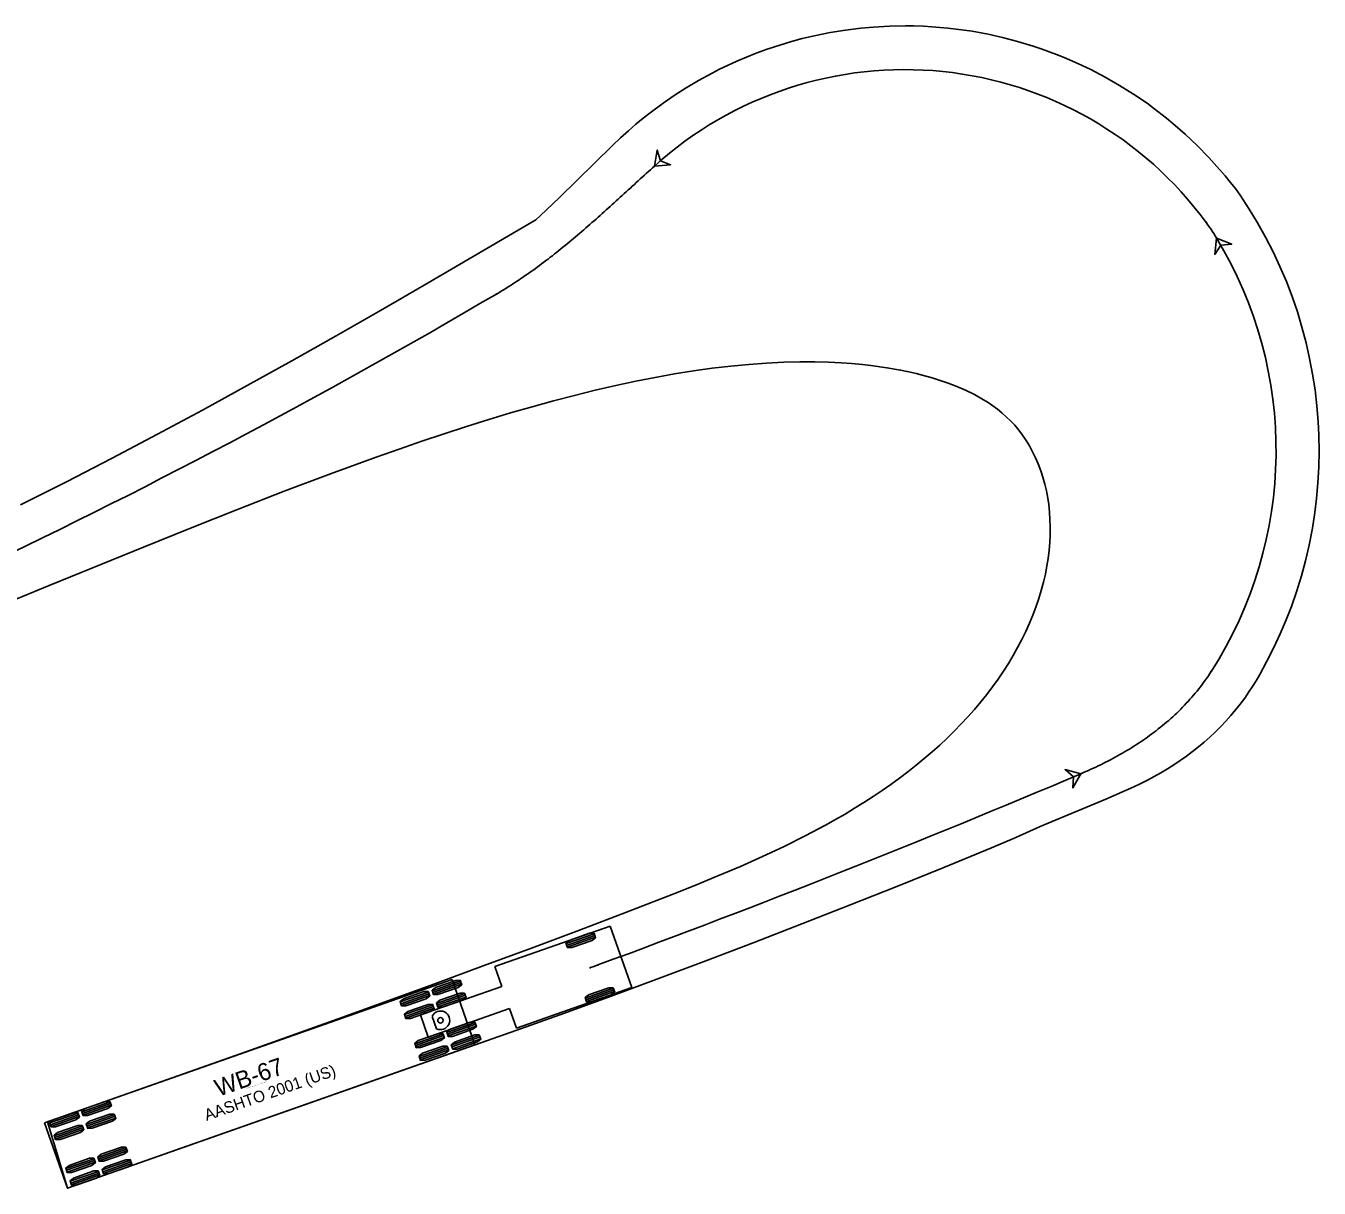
# Model space of a CAD drawing. Extents: x 2175591 to 2194071, y 76570 to 86955.
# Drawn here: x 2193912.2 to 2194070.9, y 86806.6 to 86949.2 of the extents above; entities that cross this region are included whole.
import ezdxf

# ---------------------------------------------------------------- set-up
doc = ezdxf.new("R2010")
doc.units = 0
doc.layers.add('C-UTIL-STRM-TEXT', color=7, linetype='Continuous')

msp = doc.modelspace()

# ---------------------------------------------------------------- linework, layer by layer
at = {"layer": 'C-UTIL-STRM-TEXT'}
for p, q in [((2193983.91, 86838.76), (2193969.76, 86833.78)), ((2193981.95, 86837.82), (2193978.49, 86836.6)), ((2193982.02, 86837.6), (2193978.56, 86836.39)), ((2193982.1, 86837.39), (2193978.64, 86836.17)), ((2193986.57, 86831.21), (2193983.91, 86838.76)), ((2193983.91, 86838.76), (2193983.91, 86838.76)), ((2193969.76, 86833.78), (2193970.61, 86831.36)), ((2193964.49, 86832.19), (2193914.49, 86814.61)), ((2193970.61, 86831.36), (2193960.63, 86827.85)), ((2193965.51, 86832.04), (2193962.06, 86830.83)), ((2193965.59, 86831.83), (2193962.13, 86830.61)), ((2193965.67, 86831.61), (2193962.21, 86830.4)), ((2193967.31, 86824.17), (2193964.49, 86832.19)), ((2193964.49, 86832.19), (2193964.49, 86832.19)), ((2193972.42, 86826.23), (2193986.57, 86831.21)), ((2193984.29, 86831.14), (2193980.84, 86829.92)), ((2193961.58, 86830.66), (2193958.12, 86829.45)), ((2193961.66, 86830.45), (2193958.2, 86829.23)), ((2193961.74, 86830.23), (2193958.28, 86829.01)), ((2193966.06, 86830.49), (2193962.6, 86829.27)), ((2193966.14, 86830.27), (2193962.68, 86829.06)), ((2193966.21, 86830.05), (2193962.75, 86828.84)), ((2193984.37, 86830.92), (2193980.91, 86829.71)), ((2193984.45, 86830.71), (2193980.99, 86829.49)), ((2193962.13, 86829.11), (2193958.67, 86827.89)), ((2193962.21, 86828.89), (2193958.75, 86827.67)), ((2193962.28, 86828.67), (2193958.82, 86827.46)), ((2193960.63, 86827.85), (2193961.58, 86825.14)), ((2193961.58, 86825.14), (2193971.56, 86828.65)), ((2193971.56, 86828.65), (2193972.42, 86826.23)), ((2193962.04, 86827.68), (2193962.58, 86826.16)), ((2193967.32, 86826.92), (2193963.86, 86825.7)), ((2193967.39, 86826.7), (2193963.93, 86825.49)), ((2193967.47, 86826.49), (2193964.01, 86825.27)), ((2193963.39, 86825.54), (2193959.93, 86824.32)), ((2193963.46, 86825.32), (2193960, 86824.1)), ((2193963.54, 86825.1), (2193960.08, 86823.89)), ((2193967.86, 86825.36), (2193964.4, 86824.15)), ((2193967.94, 86825.15), (2193964.48, 86823.93)), ((2193968.02, 86824.93), (2193964.56, 86823.71)), ((2193917.31, 86806.59), (2193967.31, 86824.17)), ((2193963.93, 86823.98), (2193960.47, 86822.76)), ((2193964.01, 86823.76), (2193960.55, 86822.55)), ((2193964.08, 86823.55), (2193960.63, 86822.33)), ((2193922.51, 86817.19), (2193919.05, 86815.97)), ((2193922.58, 86816.97), (2193919.12, 86815.76)), ((2193922.66, 86816.76), (2193919.2, 86815.54)), ((2193918.58, 86815.81), (2193915.12, 86814.59)), ((2193918.65, 86815.59), (2193915.19, 86814.37)), ((2193918.73, 86815.37), (2193915.27, 86814.16)), ((2193923.05, 86815.63), (2193919.6, 86814.42)), ((2193923.13, 86815.42), (2193919.67, 86814.2)), ((2193923.21, 86815.2), (2193919.75, 86813.98)), ((2193914.49, 86814.61), (2193917.31, 86806.59)), ((2193919.12, 86814.25), (2193915.66, 86813.03)), ((2193919.2, 86814.03), (2193915.74, 86812.82)), ((2193919.28, 86813.82), (2193915.82, 86812.6)), ((2193924.47, 86811.59), (2193921.02, 86810.37)), ((2193924.55, 86811.37), (2193921.09, 86810.16)), ((2193924.63, 86811.16), (2193921.17, 86809.94)), ((2193920.54, 86810.21), (2193917.09, 86808.99)), ((2193920.62, 86809.99), (2193917.16, 86808.78)), ((2193920.7, 86809.78), (2193917.24, 86808.56)), ((2193925.02, 86810.03), (2193921.56, 86808.82)), ((2193925.1, 86809.82), (2193921.64, 86808.6)), ((2193925.17, 86809.6), (2193921.72, 86808.39)), ((2193921.09, 86808.65), (2193917.63, 86807.44)), ((2193921.17, 86808.44), (2193917.71, 86807.22)), ((2193921.24, 86808.22), (2193917.78, 86807))]:
    msp.add_line(p, q, dxfattribs=at)
for points in [[(2193911.53, 86890.46), (2193917.16, 86893.3), (2193922.77, 86896.2), (2193928.34, 86899.13), (2193933.87, 86902.1), (2193939.35, 86905.1), (2193944.81, 86908.13), (2193950.27, 86911.22), (2193955.7, 86914.33), (2193961.07, 86917.44), (2193974.76, 86925.45), (2193975.34, 86925.96), (2193977.64, 86928.13), (2193979.87, 86930.3), (2193984.16, 86934.53), (2193985.17, 86935.49), (2193986.14, 86936.37), (2193987.07, 86937.18), (2193987.96, 86937.92), (2193988.82, 86938.59), (2193990.42, 86939.78), (2193991.89, 86940.79), (2193993.24, 86941.65), (2193994.73, 86942.53), (2193996.43, 86943.45), (2193997.34, 86943.92), (2193998.29, 86944.38), (2193999.45, 86944.9), (2194000.64, 86945.41), (2194001.84, 86945.89), (2194003.18, 86946.38), (2194004.71, 86946.88), (2194006.16, 86947.32), (2194007.49, 86947.68), (2194009.16, 86948.07), (2194010.92, 86948.42), (2194012.77, 86948.72), (2194014.69, 86948.96), (2194016.22, 86949.1), (2194018.17, 86949.21), (2194020.14, 86949.25), (2194021.12, 86949.24), (2194022.37, 86949.2), (2194023.37, 86949.14), (2194025.36, 86948.97), (2194026.36, 86948.86), (2194028.34, 86948.58), (2194030.31, 86948.21), (2194032.05, 86947.83), (2194033.91, 86947.34), (2194035.84, 86946.76), (2194036.8, 86946.44), (2194038.7, 86945.74), (2194039.64, 86945.36), (2194041.3, 86944.64), (2194042.9, 86943.88), (2194044.68, 86942.95), (2194046.43, 86941.94), (2194048.13, 86940.87), (2194049.8, 86939.74), (2194050.61, 86939.14), (2194052.21, 86937.91), (2194052.98, 86937.27), (2194054.5, 86935.94), (2194055.97, 86934.55), (2194057.38, 86933.11), (2194058.06, 86932.37), (2194059.38, 86930.85), (2194060.02, 86930.07), (2194060.64, 86929.27), (2194061.23, 86928.45), (2194062.34, 86926.77), (2194063.38, 86925.06), (2194064.36, 86923.31), (2194065.27, 86921.52), (2194066.12, 86919.72), (2194066.9, 86917.88), (2194067.61, 86916.03), (2194068.25, 86914.15), (2194068.82, 86912.26), (2194069.33, 86910.35), (2194069.76, 86908.43), (2194070.13, 86906.51), (2194070.42, 86904.57), (2194070.65, 86902.63), (2194070.81, 86900.68), (2194070.89, 86899.01), (2194070.93, 86897.05), (2194070.89, 86895.1), (2194070.78, 86893.16), (2194070.61, 86891.22), (2194070.4, 86889.51), (2194070.1, 86887.59), (2194069.7, 86885.52), (2194069.25, 86883.6), (2194068.75, 86881.74), (2194068.14, 86879.78), (2194067.52, 86877.99), (2194066.88, 86876.34), (2194066.15, 86874.63), (2194065.37, 86872.93), (2194064.52, 86871.27), (2194063.64, 86869.65), (2194063.18, 86868.86), (2194062.75, 86868.16), (2194062.31, 86867.5), (2194061.79, 86866.75), (2194061.25, 86866.01), (2194060.68, 86865.29), (2194060.09, 86864.59), (2194059.47, 86863.91), (2194058.84, 86863.24), (2194058.19, 86862.59), (2194057.51, 86861.95), (2194056.82, 86861.34), (2194056.11, 86860.74), (2194055.38, 86860.17), (2194054.64, 86859.61), (2194053.88, 86859.07), (2194053.1, 86858.55), (2194052.31, 86858.05), (2194051.51, 86857.57), (2194050.69, 86857.1), (2194049.87, 86856.66), (2194049.03, 86856.24), (2194048.18, 86855.83), (2194044.76, 86854.35), (2194036.7, 86850.96), (2194033.7, 86849.62), (2194030.72, 86848.35), (2194024.84, 86845.94), (2194019.07, 86843.62), (2194013.3, 86841.32), (2194007.42, 86839.02), (2194001.44, 86836.71), (2193995.66, 86834.51), (2193989.63, 86832.25), (2193983.69, 86830.05), (2193977.72, 86827.88), (2193971.76, 86825.75), (2193917.31, 86806.59), (2193914.83, 86814.73), (2193914.83, 86814.73)], [(2193989.33, 86932.03), (2193989.08, 86931.81), (2193988.84, 86931.59), (2193988.59, 86931.36), (2193988.34, 86931.14), (2193988.1, 86930.91), (2193987.85, 86930.69), (2193987.6, 86930.46), (2193987.36, 86930.24), (2193987.11, 86930.01), (2193986.87, 86929.79), (2193986.62, 86929.56), (2193986.38, 86929.34), (2193986.13, 86929.11), (2193985.88, 86928.89), (2193985.64, 86928.66), (2193985.39, 86928.44), (2193985.14, 86928.21), (2193984.9, 86927.99), (2193984.65, 86927.77), (2193984.4, 86927.54), (2193984.16, 86927.32), (2193983.91, 86927.09), (2193983.66, 86926.87), (2193983.42, 86926.65), (2193983.17, 86926.42), (2193982.92, 86926.2), (2193982.67, 86925.98), (2193982.42, 86925.76), (2193982.17, 86925.54), (2193981.92, 86925.32), (2193981.67, 86925.1), (2193981.42, 86924.88), (2193981.17, 86924.66), (2193980.92, 86924.44), (2193980.67, 86924.22), (2193980.41, 86924), (2193980.16, 86923.79), (2193979.91, 86923.57), (2193979.65, 86923.36), (2193979.4, 86923.14), (2193979.14, 86922.93), (2193978.88, 86922.71), (2193978.63, 86922.5), (2193978.37, 86922.29), (2193978.11, 86922.08), (2193977.85, 86921.87), (2193977.59, 86921.66), (2193977.33, 86921.45), (2193977.07, 86921.25), (2193976.81, 86921.04), (2193976.54, 86920.84), (2193976.28, 86920.63), (2193976.02, 86920.43), (2193975.75, 86920.23), (2193975.48, 86920.03), (2193975.22, 86919.83), (2193974.95, 86919.63), (2193974.68, 86919.44), (2193974.41, 86919.24), (2193974.14, 86919.05), (2193973.86, 86918.86), (2193973.59, 86918.67), (2193973.32, 86918.48), (2193973.04, 86918.29), (2193972.76, 86918.1), (2193972.49, 86917.92), (2193972.21, 86917.74), (2193971.93, 86917.55), (2193971.65, 86917.38), (2193971.37, 86917.2), (2193971.08, 86917.02), (2193970.8, 86916.85), (2193970.51, 86916.67), (2193970.23, 86916.5), (2193969.94, 86916.33)], [(2194058.34, 86923.19), (2194058.16, 86923.48), (2194057.99, 86923.76), (2194057.81, 86924.04), (2194057.62, 86924.32), (2194057.43, 86924.59), (2194057.24, 86924.87), (2194057.05, 86925.14)], [(2193914.83, 86814.73), (2193938.63, 86823.12), (2193950.52, 86827.37), (2193962.39, 86831.68), (2193968.32, 86833.86), (2193974.23, 86836.06), (2193980.13, 86838.27), (2193985.92, 86840.47), (2193991.7, 86842.71), (2193994.3, 86843.75), (2193997.12, 86844.91), (2193999.9, 86846.09), (2194002.62, 86847.3), (2194005.27, 86848.54), (2194007.85, 86849.83), (2194010.34, 86851.15), (2194011.56, 86851.83), (2194012.74, 86852.51), (2194013.91, 86853.21), (2194015.05, 86853.92), (2194016.17, 86854.65), (2194017.28, 86855.39), (2194018.36, 86856.14), (2194019.42, 86856.91), (2194020.45, 86857.7), (2194021.47, 86858.5), (2194022.45, 86859.31), (2194023.42, 86860.13), (2194024.35, 86860.97), (2194025.26, 86861.82), (2194026.14, 86862.69), (2194027, 86863.57), (2194027.82, 86864.46), (2194028.62, 86865.36), (2194029.39, 86866.28), (2194030.13, 86867.2), (2194030.84, 86868.14), (2194031.52, 86869.08), (2194032.17, 86870.04), (2194032.78, 86871), (2194033.37, 86871.97), (2194033.92, 86872.95), (2194034.43, 86873.93), (2194034.92, 86874.92), (2194035.37, 86875.92), (2194035.78, 86876.92), (2194036.16, 86877.92), (2194036.51, 86878.95), (2194036.82, 86879.95), (2194037.09, 86880.96), (2194037.32, 86881.96), (2194037.51, 86882.96), (2194037.66, 86883.88), (2194037.78, 86884.88), (2194037.86, 86885.84), (2194037.91, 86886.79), (2194037.92, 86887.74), (2194037.89, 86888.66), (2194037.83, 86889.58), (2194037.73, 86890.49), (2194037.61, 86891.28), (2194037.45, 86892.16), (2194037.25, 86893.01), (2194037.02, 86893.84), (2194036.76, 86894.65), (2194036.45, 86895.48), (2194036.12, 86896.24), (2194035.76, 86896.98), (2194035.38, 86897.69), (2194034.96, 86898.37), (2194034.52, 86899.01), (2194034.06, 86899.63), (2194033.57, 86900.22), (2194033.06, 86900.77), (2194032.53, 86901.28), (2194031.99, 86901.76), (2194031.43, 86902.21), (2194030.87, 86902.62), (2194030.3, 86903.01), (2194029.73, 86903.36), (2194028.61, 86903.99), (2194027.51, 86904.53), (2194026.44, 86904.99), (2194025.41, 86905.39), (2194024.41, 86905.74), (2194023.44, 86906.04), (2194022.36, 86906.35), (2194021.46, 86906.58), (2194020.57, 86906.78), (2194019.55, 86907), (2194017.88, 86907.29), (2194015.91, 86907.57), (2194014.89, 86907.68), (2194013.54, 86907.81), (2194012.25, 86907.9), (2194010.7, 86907.97), (2194009.04, 86908.01), (2194007.19, 86908.01), (2194005.21, 86907.96), (2194003.09, 86907.86), (2194000.92, 86907.7), (2193998.7, 86907.48), (2193996.43, 86907.22), (2193994.13, 86906.89), (2193991.8, 86906.52), (2193989.44, 86906.1), (2193987.04, 86905.63), (2193984.59, 86905.1), (2193982.08, 86904.53), (2193979.54, 86903.9), (2193976.95, 86903.23), (2193974.33, 86902.5), (2193971.67, 86901.74), (2193968.99, 86900.93), (2193966.27, 86900.08), (2193963.53, 86899.19), (2193960.78, 86898.26), (2193958, 86897.31), (2193955.2, 86896.32), (2193949.57, 86894.27), (2193943.88, 86892.12), (2193938.14, 86889.89), (2193932.39, 86887.61), (2193926.62, 86885.28), (2193915.05, 86880.55), (2193880.18, 86866.2)], [(2194041.69, 86857.46), (2194041.99, 86857.6), (2194042.3, 86857.73), (2194042.6, 86857.86), (2194042.91, 86858), (2194043.21, 86858.14), (2194043.51, 86858.28), (2194043.82, 86858.42), (2194044.12, 86858.56), (2194044.42, 86858.71), (2194044.71, 86858.86), (2194045.01, 86859.01), (2194045.31, 86859.16), (2194045.6, 86859.32), (2194045.89, 86859.48), (2194046.19, 86859.64), (2194046.48, 86859.8), (2194046.77, 86859.97), (2194047.05, 86860.14), (2194047.34, 86860.31), (2194047.63, 86860.48), (2194047.91, 86860.65), (2194048.19, 86860.83), (2194048.47, 86861.01), (2194048.75, 86861.19), (2194049.03, 86861.38), (2194049.31, 86861.56), (2194049.58, 86861.75), (2194049.85, 86861.95), (2194050.12, 86862.14), (2194050.39, 86862.34), (2194050.66, 86862.54), (2194050.92, 86862.74), (2194051.18, 86862.95), (2194051.44, 86863.16), (2194051.7, 86863.37), (2194051.96, 86863.58), (2194052.21, 86863.8), (2194052.46, 86864.01), (2194052.71, 86864.24), (2194052.96, 86864.46), (2194053.21, 86864.69), (2194053.45, 86864.91), (2194053.69, 86865.15), (2194053.93, 86865.38), (2194054.16, 86865.62), (2194054.39, 86865.86), (2194054.62, 86866.1), (2194054.85, 86866.34), (2194055.07, 86866.59), (2194055.29, 86866.84), (2194055.51, 86867.09), (2194055.72, 86867.35), (2194055.94, 86867.6), (2194056.14, 86867.86), (2194056.35, 86868.13), (2194056.55, 86868.39), (2194056.75, 86868.66), (2194056.95, 86868.93), (2194057.14, 86869.2), (2194057.33, 86869.48), (2194057.51, 86869.75), (2194057.69, 86870.03)], [(2193981.47, 86833.66), (2193981.78, 86833.77), (2193982.09, 86833.88), (2193982.41, 86833.99)]]:
    msp.add_lwpolyline(points, dxfattribs=at)
for points in [[(2193989.33, 86932.03), (2193991.32, 86932.2), (2193990.07, 86932.7), (2193989.69, 86934)], [(2194058.34, 86923.19), (2194058.12, 86921.2), (2194058.86, 86922.34), (2194060.2, 86922.47)], [(2194041.69, 86857.46), (2194039.75, 86857.97), (2194040.77, 86857.07), (2194040.7, 86855.72)], [(2193981.93, 86837.87), (2193982.12, 86837.33), (2193981.69, 86837), (2193979.2, 86836.13), (2193978.66, 86836.12), (2193978.47, 86836.66), (2193978.89, 86836.99), (2193981.38, 86837.87)], [(2193965.5, 86832.1), (2193965.69, 86831.56), (2193965.26, 86831.23), (2193962.77, 86830.35), (2193962.23, 86830.34), (2193962.04, 86830.88), (2193962.46, 86831.21), (2193964.95, 86832.09)], [(2193984.28, 86831.19), (2193984.47, 86830.65), (2193984.04, 86830.32), (2193981.55, 86829.44), (2193981.01, 86829.44), (2193980.82, 86829.98), (2193981.24, 86830.31), (2193983.73, 86831.18)], [(2193961.56, 86830.72), (2193961.75, 86830.18), (2193961.33, 86829.84), (2193958.84, 86828.97), (2193958.3, 86828.96), (2193958.11, 86829.5), (2193958.53, 86829.83), (2193961.02, 86830.71)], [(2193966.04, 86830.54), (2193966.23, 86830), (2193965.81, 86829.67), (2193963.31, 86828.79), (2193962.77, 86828.79), (2193962.58, 86829.32), (2193963.01, 86829.66), (2193965.5, 86830.53)], [(2193962.11, 86829.16), (2193962.3, 86828.62), (2193961.87, 86828.29), (2193959.38, 86827.41), (2193958.84, 86827.4), (2193958.65, 86827.94), (2193959.08, 86828.28), (2193961.57, 86829.15)], [(2193967.3, 86826.97), (2193967.49, 86826.43), (2193967.06, 86826.1), (2193964.57, 86825.22), (2193964.03, 86825.22), (2193963.84, 86825.76), (2193964.27, 86826.09), (2193966.76, 86826.96)], [(2193963.37, 86825.59), (2193963.56, 86825.05), (2193963.13, 86824.72), (2193960.64, 86823.84), (2193960.1, 86823.83), (2193959.91, 86824.37), (2193960.33, 86824.71), (2193962.83, 86825.58)], [(2193967.84, 86825.42), (2193968.03, 86824.88), (2193967.61, 86824.54), (2193965.12, 86823.67), (2193964.58, 86823.66), (2193964.39, 86824.2), (2193964.81, 86824.53), (2193967.3, 86825.41)], [(2193963.91, 86824.03), (2193964.1, 86823.49), (2193963.68, 86823.16), (2193961.19, 86822.29), (2193960.64, 86822.28), (2193960.45, 86822.82), (2193960.88, 86823.15), (2193963.37, 86824.03)], [(2193922.49, 86817.24), (2193922.68, 86816.7), (2193922.25, 86816.37), (2193919.76, 86815.49), (2193919.22, 86815.49), (2193919.03, 86816.03), (2193919.46, 86816.36), (2193921.95, 86817.23)], [(2193918.56, 86815.86), (2193918.75, 86815.32), (2193918.32, 86814.99), (2193915.83, 86814.11), (2193915.29, 86814.1), (2193915.1, 86814.64), (2193915.53, 86814.98), (2193918.02, 86815.85)], [(2193923.04, 86815.69), (2193923.23, 86815.15), (2193922.8, 86814.81), (2193920.31, 86813.94), (2193919.77, 86813.93), (2193919.58, 86814.47), (2193920, 86814.8), (2193922.49, 86815.68)], [(2193919.1, 86814.3), (2193919.29, 86813.76), (2193918.87, 86813.43), (2193916.38, 86812.56), (2193915.84, 86812.55), (2193915.65, 86813.09), (2193916.07, 86813.42), (2193918.56, 86814.3)], [(2193924.46, 86811.64), (2193924.65, 86811.11), (2193924.22, 86810.77), (2193921.73, 86809.9), (2193921.19, 86809.89), (2193921, 86810.43), (2193921.42, 86810.76), (2193923.91, 86811.64)], [(2193920.53, 86810.26), (2193920.72, 86809.72), (2193920.29, 86809.39), (2193917.8, 86808.51), (2193917.26, 86808.51), (2193917.07, 86809.05), (2193917.49, 86809.38), (2193919.98, 86810.26)], [(2193925, 86810.09), (2193925.19, 86809.55), (2193924.77, 86809.22), (2193922.28, 86808.34), (2193921.73, 86808.33), (2193921.54, 86808.87), (2193921.97, 86809.2), (2193924.46, 86810.08)], [(2193921.07, 86808.71), (2193921.26, 86808.17), (2193920.84, 86807.83), (2193918.34, 86806.96), (2193917.8, 86806.95), (2193917.61, 86807.49), (2193918.04, 86807.82), (2193920.53, 86808.7)]]:
    msp.add_lwpolyline(points, close=True, dxfattribs=at)
for centre, radius in [((2193989.33, 86932.03), 0.0417), ((2193989.33, 86932.03), 0.0417), ((2194057.05, 86925.14), 0.0417), ((2194057.05, 86925.14), 0.0417), ((2194058.34, 86923.19), 0.0417), ((2194058.34, 86923.19), 0.0417), ((2193969.94, 86916.33), 0.0417), ((2193969.94, 86916.33), 0.0417), ((2194057.69, 86870.03), 0.0417), ((2194057.69, 86870.03), 0.0417), ((2194041.69, 86857.46), 0.0417), ((2194041.69, 86857.46), 0.0417), ((2193981.47, 86833.66), 0.0417), ((2193982.41, 86833.99), 0.0417), ((2193982.41, 86833.99), 0.0417), ((2193963.07, 86827.19), 0.34)]:
    msp.add_circle(centre, radius, dxfattribs=at)
for centre, radius, start, end in [((2194020.08, 86898.06), 45.82, 36.2169, 132.1524), ((2194015.47, 86897.13), 50.17, 327.3146, 31.3001), ((2193551.13, 87629.03), 826.64, 290.04978, 300.44028), ((2193522.35, 88082.47), 1330.55, 290.22857, 292.97433), ((2193963.07, 86827.19), 1.14, 244.3704, 154.3704)]:
    msp.add_arc(centre, radius, start, end, dxfattribs=at)

# ---------------------------------------------------------------- texts
for s, height, p in [('AASHTO 2001 (US)', 1.4167, (2193934.38, 86814.84)), ('WB-67', 2.125, (2193935.83, 86817.79)), ('(c) 2019 Transoft Solutions, Inc. All rights reserved.', 0.085, (2193939.28, 86818.78))]:
    msp.add_text(s, height=height, rotation=19.3704, dxfattribs=at).set_placement(p)

doc.saveas('drawing.dxf')
